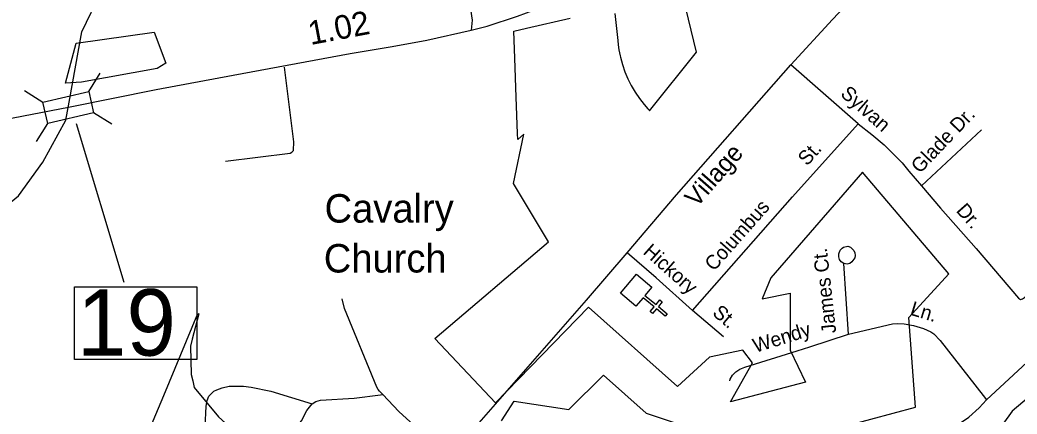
# Model space of a CAD drawing. Extents: x 2104537 to 2336408, y 34176 to 229611.
# Drawn here: x 2179113 to 2184362, y 75625 to 77701 of the extents above; entities that cross this region are included whole.
import ezdxf

# ---------------------------------------------------------------- set-up
doc = ezdxf.new("R2010")
doc.units = 0
for name, color, linetype in [('Exist Boundary Political City Limit New', 7, 'Continuous'), ('Exist Cultural Church CELL', 7, 'Continuous'), ('Exist Cultural Church Label', 7, 'Continuous'), ('Exist Hydrographic River Shore', 7, 'Continuous'), ('Exist Road Non-System Type 51', 7, 'Continuous'), ('Exist Road Non-System Type 51 Label', 7, 'Continuous'), ('Exist Road Primary NC Attributed', 7, 'Continuous'), ('Exist Road Primary NC Label', 7, 'Continuous'), ('Exist Road Primary US Attributed', 7, 'Continuous'), ('Exist Road Primary US Mileage Hundredths English Label', 7, 'Continuous'), ('Exist Road Primary US Structure Standard Bridge CELL', 7, 'Continuous'), ('Exist Road Primary US Structure Standard Bridge Number Label', 7, 'Continuous'), ('Map Preparation Boundary City Limit Buffer Line', 7, 'Continuous')]:
    doc.layers.add(name, color=color, linetype=linetype)

msp = doc.modelspace()

# ---------------------------------------------------------------- linework, layer by layer
at = {"layer": 'Exist Boundary Political City Limit New'}
for points in [[(2182244.2, 77735.4), (2182260, 77593.3), (2182262.5, 77570.2), (2182266.2, 77544.3), (2182272.8, 77511.2), (2182274.2, 77504.9), (2182284.8, 77466.1), (2182297.8, 77428.1), (2182313.2, 77391.1), (2182331.2, 77355.1), (2182351.5, 77320.5), (2182374, 77287.2), (2182398.8, 77255.5), (2182419, 77232.4), (2182425.5, 77225.5), (2182427.8, 77223.1), (2182674, 77532), (2182564.5, 77988.9)], [(2183122.8, 75471.6), (2183827, 75660.7), (2183793, 76134.3), (2184002.8, 76364.1), (2183548.8, 76899), (2183065.2, 76342.2), (2183021.2, 76232.2), (2183167.8, 76261.6), (2183167.8, 75961.1), (2183248.5, 75792.6), (2182853, 75690), (2182970, 75895.2), (2182918.8, 75961.1), (2182743, 75924.5), (2182574.8, 75770.6), (2182106, 76188.3), (2181616.8, 75684.6), (2181297.2, 76023.9), (2181896.5, 76532.8), (2181711.2, 76840.4), (2181765.8, 77098.9), (2181734, 77071.5), (2181732, 77102.3), (2181725.8, 77294.3), (2181717.8, 77500), (2181714, 77641.8), (2181780.2, 77657.5), (2182009.5, 77710.6)], [(2179438.2, 77374.1), (2179353, 77368.8), (2179409.8, 77578.4), (2179819.8, 77637), (2179882, 77473.6), (2179835.8, 77445.2), (2179438.2, 77374.1)], [(2178882.8, 75140.7), (2179132.5, 75196.1), (2179428.5, 75261.3), (2179696.2, 75320.9), (2179703, 75322.4), (2179870.5, 75723.6), (2180049.2, 76154.3), (2180055.8, 76152.2), (2180020.5, 76018.8), (2180010.5, 75982.9), (2180015.2, 75833.3), (2180023, 75799.6), (2180030.8, 75764.9), (2180158.2, 75610.7), (2180232.5, 75543.9), (2180268.8, 75535.6), (2180294, 75521.6), (2180340.8, 75494.9), (2180528.8, 75387.8), (2180548.2, 75376), (2180614.2, 75336.6), (2180861.8, 75196.2), (2180894.8, 75155.5)], [(2184709.2, 75953.8), (2184337, 75641.2), (2184207, 75459.8)], [(2181648.2, 75590), (2181715.2, 75692.5), (2182003, 75649.1), (2182184.5, 75830.6), (2182409, 75629.4), (2182838.8, 75487.4)]]:
    msp.add_lwpolyline(points, dxfattribs=at)
at = {"layer": 'Exist Cultural Church CELL'}
msp.add_lwpolyline([(2182439.9, 76294.1), (2182403.5, 76250.3), (2182461.9, 76201.5), (2182482.4, 76226.1), (2182494.7, 76215.8), (2182474.2, 76191.3), (2182520.4, 76152.7), (2182510.1, 76140.4), (2182463.9, 76179), (2182443.4, 76154.4), (2182431.2, 76164.6), (2182451.7, 76189.2), (2182393.2, 76238), (2182356.2, 76193.8), (2182274.5, 76262), (2182358.1, 76362.3)], close=True, dxfattribs=at)
at = {"layer": 'Exist Hydrographic River Shore'}
msp.add_lwpolyline([(2175255.5, 74612.6), (2175463.4, 74674.3), (2175695.3, 74781.3), (2175811.3, 74874.2), (2175894.4, 74974.3), (2176075.5, 75417), (2176167.3, 75549.1), (2176199.3, 75595.1), (2176357.8, 75720), (2176398.4, 75752), (2176714.4, 75929.7), (2176996.3, 76022.6), (2177263.3, 76024), (2177555.3, 75959.3), (2177931.4, 75794.6), (2178122.5, 75846.7), (2178371.4, 76055.1), (2178636.3, 76391.2), (2179104.9, 76775.2), (2179233.9, 76951.2), (2179354.1, 77172.8), (2179373.2, 77268.1), (2179439.2, 77637.8), (2179638.6, 78054.4)], dxfattribs=at)
at = {"layer": 'Exist Road Non-System Type 51'}
for p, q in [((2183524.9, 77154.4), (2183171.6, 77465.3)), ((2183475.6, 76046.1), (2183451, 76417.9)), ((2182816.9, 76031.6), (2182654.5, 76171.2)), ((2181023.6, 75727.9), (2181006.2, 75746.4)), ((2181011.3, 75726.4), (2181023.6, 75727.9)), ((2184184.5, 75722.2), (2184201.9, 75700))]:
    msp.add_line(p, q, dxfattribs=at)
for points in [[(2181476.3, 77817.3), (2181494.4, 77699.5), (2181488.8, 77647.4)], [(2180195.2, 76956.5), (2180535, 76999.9), (2180545.2, 77003.9), (2180552.6, 77013.3), (2180554.9, 77059.8), (2180505.3, 77451.9)], [(2182654.5, 76171.2), (2183180.2, 76769), (2183524.9, 77154.4)], [(2183524.9, 77154.4), (2183597, 77098.5), (2183663.2, 77042.8), (2183757.8, 76949.1), (2183791.7, 76905.1), (2183859, 76826.4)], [(2183859, 76826.4), (2184174.5, 77121.7)], [(2183859, 76826.4), (2183958.6, 76710), (2184147.4, 76496.4), (2184369, 76235.2), (2184380.4, 76229.1), (2184390.3, 76231.2), (2184402.2, 76239.1), (2184523.9, 76339.8), (2184586.2, 76394.6)], [(2183451, 76417.9), (2183437, 76427.4), (2183427.4, 76439.4), (2183423.8, 76453.6), (2183424.1, 76469.6), (2183430.3, 76487.6), (2183440.7, 76499.2), (2183448.7, 76504.9), (2183470.8, 76508.8), (2183484.8, 76504.2), (2183502.5, 76486.2), (2183508.1, 76473.9), (2183509.8, 76459.8), (2183507.6, 76448), (2183493.1, 76426.3), (2183481.2, 76418.3), (2183467, 76414.7), (2183451, 76417.9)], [(2182654.5, 76171.2), (2182461.6, 76342.6), (2182309.3, 76473.8)], [(2181006.2, 75746.4), (2180999.4, 75753.7), (2180991.5, 75767.6), (2180822.3, 76180.3), (2180809.9, 76232.4)], [(2183475.6, 76046.1), (2183707.3, 76100), (2183735.2, 76102.1), (2183767.3, 76100.1), (2183816.4, 76091.3), (2183869.5, 76075.2), (2183907.9, 76058.7), (2183924.8, 76047.6), (2183956.9, 76013.1), (2184184.5, 75722.2)], [(2183204, 75957.6), (2183272.2, 75978.8), (2183475.6, 76046.1)], [(2182849.4, 75799.8), (2182852.6, 75809.4), (2182865.1, 75829.5), (2182881.9, 75847.9), (2182902.1, 75861.3), (2182928.9, 75872.2), (2183204, 75957.6)], [(2184201.9, 75700), (2184438.7, 75919.2), (2184519.9, 75991.9)], [(2180100.6, 75471.1), (2180093.3, 75503.1), (2180088.2, 75558), (2180094.2, 75667.1), (2180099.7, 75697.2), (2180108, 75719.7), (2180133.5, 75745.1), (2180149.7, 75753.3), (2180177.4, 75763.6), (2180215.3, 75771.4), (2180290.1, 75771.9), (2180331.4, 75766.9), (2180433.7, 75745.6), (2180652.2, 75679.3)], [(2180652.2, 75679.3), (2180671.5, 75690.8), (2180695.9, 75697.5), (2180871.9, 75708.9), (2181011.3, 75726.4)], [(2181383.4, 75400.4), (2181225.1, 75531.4), (2181108.4, 75638.7), (2181023.6, 75727.9)], [(2184043.1, 75564.3), (2184108.6, 75608.6), (2184162.7, 75657.1), (2184201.9, 75700)], [(2180100.6, 75471.1), (2180112.7, 75484), (2180129.2, 75493.2), (2180149.3, 75493.5), (2180167.4, 75483.6), (2180212.1, 75431.9), (2180244.3, 75403.7), (2180262.2, 75394.2), (2180280.1, 75388.3), (2180316.2, 75386.6), (2180332, 75390.9), (2180349.5, 75397.8), (2180392, 75425.2), (2180465.4, 75485.7), (2180547.1, 75536.3), (2180563.1, 75550.5), (2180578.8, 75566.6), (2180594.7, 75588.9), (2180624.3, 75643.1), (2180652.2, 75679.3)]]:
    msp.add_lwpolyline(points, dxfattribs=at)
at = {"layer": 'Exist Road Primary NC Attributed'}
msp.add_lwpolyline([(2181148.2, 75081.7), (2181199.6, 75167.4), (2181239.5, 75224.5), (2181305.2, 75310.1), (2181359.4, 75387.3), (2181413.6, 75447.2), (2181464.8, 75503.2), (2181507, 75551.6), (2181519.3, 75565.6), (2182096.2, 76225.9), (2182309.3, 76473.8), (2182570.1, 76779.1), (2183171.6, 77465.3), (2183390.8, 77703.9), (2183603.9, 77930.8), (2183777.2, 78121.6), (2183880.9, 78241.7)], dxfattribs=at)
at = {"layer": 'Exist Road Primary US Attributed'}
for points in [[(2181572.8, 77667.8), (2181732.7, 77720.2), (2181826.5, 77756.7), (2181906.3, 77791), (2182002.3, 77837.3), (2182052, 77863.6), (2182131.9, 77903.7), (2182279.5, 77988.2), (2182423.3, 78078.6), (2182526, 78155.8), (2182613.8, 78225.2), (2182784.8, 78370.8), (2182988.2, 78574.3), (2183228.7, 78803.8), (2183936, 79518.2), (2184686.9, 80274.7)], [(2179368.3, 77240.9), (2179829.9, 77334.4), (2180236.6, 77410.7), (2180850.8, 77524), (2181072.5, 77561.6), (2181254.8, 77594.6), (2181488.8, 77647.4), (2181572.8, 77667.8)], [(2177269.3, 76932.5), (2177318.8, 76922.8), (2177422.2, 76918), (2177533.1, 76920.3), (2177674.1, 76938.8), (2178055.4, 77001.2), (2178412.4, 77068.5), (2178792.5, 77133.9), (2178844.5, 77142.1), (2179031.8, 77177.4), (2179368.3, 77240.9)]]:
    msp.add_lwpolyline(points, dxfattribs=at)
at = {"layer": 'Exist Road Primary US Structure Standard Bridge CELL'}
for p, q in [((2179475.4, 77324), (2179535.3, 77420)), ((2179137.7, 77328.6), (2179233.7, 77268.7)), ((2179500.9, 77213.8), (2179596.9, 77153.8)), ((2179199.9, 77059.9), (2179259.8, 77155.9))]:
    msp.add_line(p, q, dxfattribs=at)
msp.add_lwpolyline([(2179233.7, 77268.7), (2179475.2, 77324.6), (2179501.3, 77211.7), (2179259.8, 77155.9)], close=True, dxfattribs=at)
at = {"layer": 'Exist Road Primary US Structure Standard Bridge Number Label'}
msp.add_line((2179408.6, 77156.1), (2179660.3, 76320.1), dxfattribs=at)
msp.add_lwpolyline([(2179401.2, 76295.5), (2180045.3, 76295.5), (2180045.3, 75913.2), (2179401.2, 75913.2)], close=True, dxfattribs=at)
at = {"layer": 'Map Preparation Boundary City Limit Buffer Line'}
for points in [[(2182244.2, 77735.4), (2182260, 77593.3), (2182262.5, 77570.2), (2182266.2, 77544.3), (2182272.8, 77511.2), (2182274.2, 77504.9), (2182284.8, 77466.1), (2182297.8, 77428.1), (2182313.2, 77391.1), (2182331.2, 77355.1), (2182351.5, 77320.5), (2182374, 77287.2), (2182398.8, 77255.5), (2182419, 77232.4), (2182425.5, 77225.5), (2182427.8, 77223.1), (2182674, 77532), (2182564.5, 77988.9)], [(2183122.8, 75471.6), (2183827, 75660.7), (2183793, 76134.3), (2184002.8, 76364.1), (2183548.8, 76899), (2183065.2, 76342.2), (2183021.2, 76232.2), (2183167.8, 76261.6), (2183167.8, 75961.1), (2183248.5, 75792.6), (2182853, 75690), (2182970, 75895.2), (2182918.8, 75961.1), (2182743, 75924.5), (2182574.8, 75770.6), (2182106, 76188.3), (2181616.8, 75684.6), (2181297.2, 76023.9), (2181896.5, 76532.8), (2181711.2, 76840.4), (2181765.8, 77098.9), (2181734, 77071.5), (2181732, 77102.3), (2181725.8, 77294.3), (2181717.8, 77500), (2181714, 77641.8), (2181780.2, 77657.5), (2182009.5, 77710.6)], [(2179438.2, 77374.1), (2179353, 77368.8), (2179409.8, 77578.4), (2179819.8, 77637), (2179882, 77473.6), (2179835.8, 77445.2), (2179438.2, 77374.1)], [(2178882.8, 75140.7), (2179132.5, 75196.1), (2179428.5, 75261.3), (2179696.2, 75320.9), (2179703, 75322.4), (2179870.5, 75723.6), (2180049.2, 76154.3), (2180055.8, 76152.2), (2180020.5, 76018.8), (2180010.5, 75982.9), (2180015.2, 75833.3), (2180023, 75799.6), (2180030.8, 75764.9), (2180158.2, 75610.7), (2180232.5, 75543.9), (2180268.8, 75535.6), (2180294, 75521.6), (2180340.8, 75494.9), (2180528.8, 75387.8), (2180548.2, 75376), (2180614.2, 75336.6), (2180861.8, 75196.2), (2180894.8, 75155.5)], [(2184709.2, 75953.8), (2184337, 75641.2), (2184207, 75459.8)], [(2181648.2, 75590), (2181715.2, 75692.5), (2182003, 75649.1), (2182184.5, 75830.6), (2182409, 75629.4), (2182838.8, 75487.4)]]:
    msp.add_lwpolyline(points, dxfattribs=at)

# ---------------------------------------------------------------- texts
at = {"layer": 'Exist Cultural Church Label'}
for s, p in [('Cavalry', (2180717, 76633.6)), ('Church', (2180712.8, 76370.7))]:
    msp.add_text(s, height=150, dxfattribs=at).set_placement(p)
at = {"layer": 'Exist Road Non-System Type 51 Label'}
for s, rotation, p in [('Sylvan', 318.6431, (2183428.1, 77305.2)), ('Glade Dr.', 46.3591, (2183850.7, 76888.5)), ('St.', 48.19, (2183256.9, 76928.6)), ('Columbus', 48.6738, (2182766.7, 76373.8)), ('Dr.', 311.4688, (2184037.8, 76694.6)), ('Hickory', 318.3793, (2182388.9, 76473)), ('James Ct.', 96.335, (2183410.6, 76053.7)), ('Ln.', 343.1339, (2183794.6, 76149.3)), ('St.', 319.3018, (2182753.5, 76150.9)), ('Wendy', 17.2456, (2182985.2, 75947.3))]:
    msp.add_text(s, height=75, rotation=rotation, dxfattribs=at).set_placement(p)
at = {"layer": 'Exist Road Primary NC Label'}
msp.add_text('Village', height=95, rotation=48.7638, dxfattribs=at).set_placement((2182675.7, 76709.4))
at = {"layer": 'Exist Road Primary US Mileage Hundredths English Label'}
msp.add_text('1.02', height=125, rotation=10.6244, dxfattribs=at).set_placement((2180643, 77568.7))
at = {"layer": 'Exist Road Primary US Structure Standard Bridge Number Label'}
msp.add_text('19', height=350, dxfattribs=at).set_placement((2179413.7, 75932.9))

doc.saveas('drawing.dxf')
